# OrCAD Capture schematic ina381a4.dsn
size A
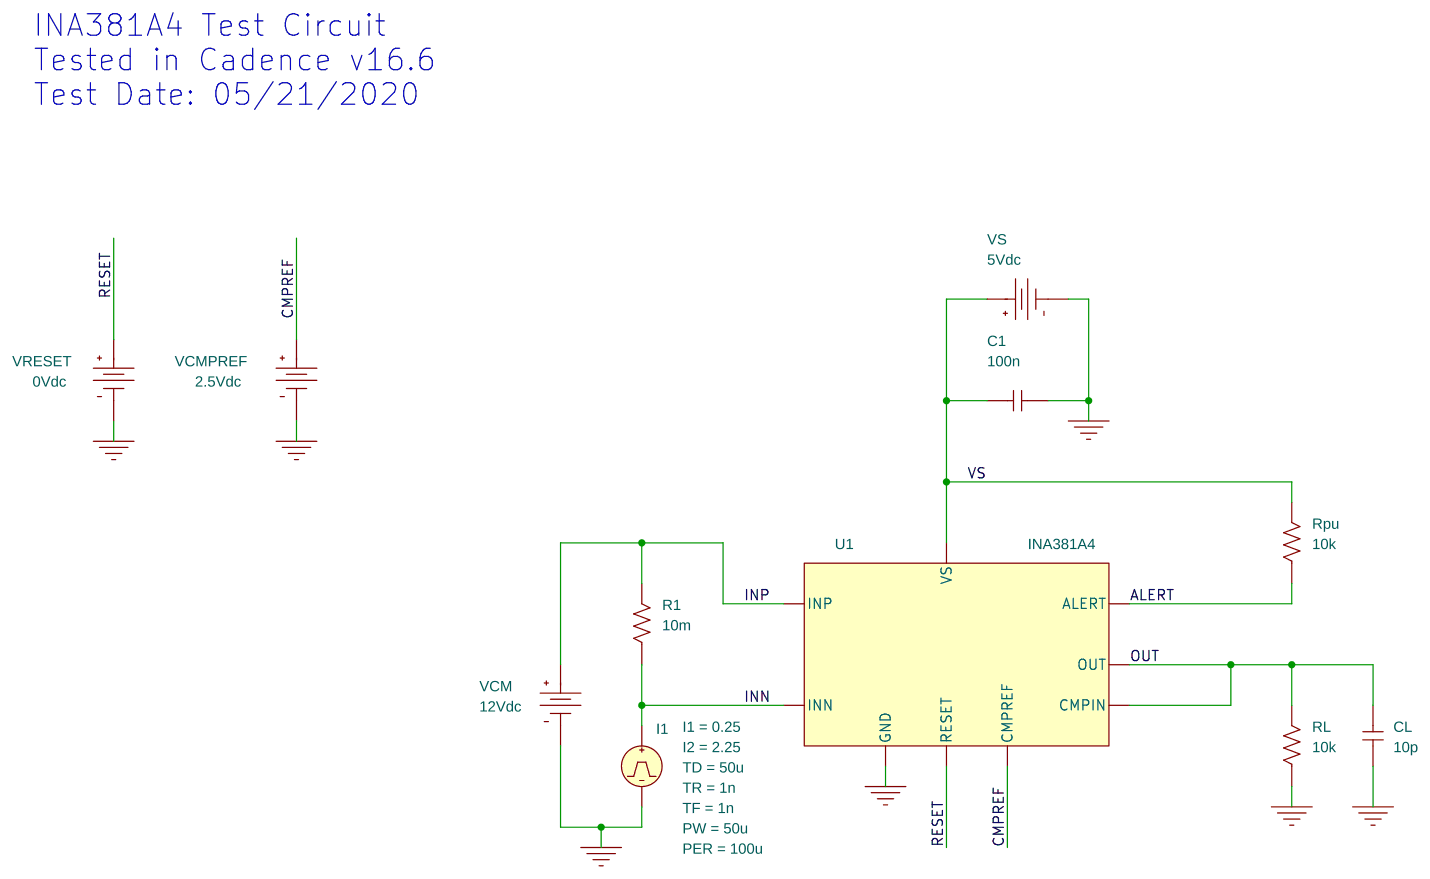
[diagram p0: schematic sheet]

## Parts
C1  100n  [RAD/CK05]
CL  10p  [RAD/CK05]
I1  IPULSE
R1  10m  [AX/RC05]
RL  10k  [AX/RC05]
Rpu  10k  [AX/RC05]
U1  INA381A4
VCM  VDC
VCMPREF  VDC
VRESET  VDC
VS  VDC

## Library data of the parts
C1 CL = C
I1 = IPULSE: I1: 0.25; I2: 2.25; PER: 100u; PW: 50u; TD: 50u; TF: 1n; TR: 1n
R1 RL Rpu = R
U1 = INA381A4
VCM = VDC: DC: 12Vdc
VCMPREF = VDC: DC: 2.5Vdc
VRESET = VDC: DC: 0Vdc
VS = VDC: DC: 5Vdc

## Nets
0: C1.2 CL.1 I1.2(-) RL.1 U1.GND VCM.1(-) VCMPREF.1(-) VRESET.1(-) VS.1(-)
ALERT: Rpu.1 U1.ALERT
CMPREF: U1.CMPREF VCMPREF.0(+)
INN: I1.1(+) R1.1 U1.INN
INP: R1.2 U1.INP VCM.0(+)
OUT: CL.2 RL.2 U1.CMPIN U1.OUT
RESET: U1.RESET VRESET.0(+)
VS: C1.1 Rpu.2 U1.VS VS.0(+)

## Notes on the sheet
- INA381A4 Test Circuit
  Tested in Cadence v16.6
  Test Date: 05/21/2020
